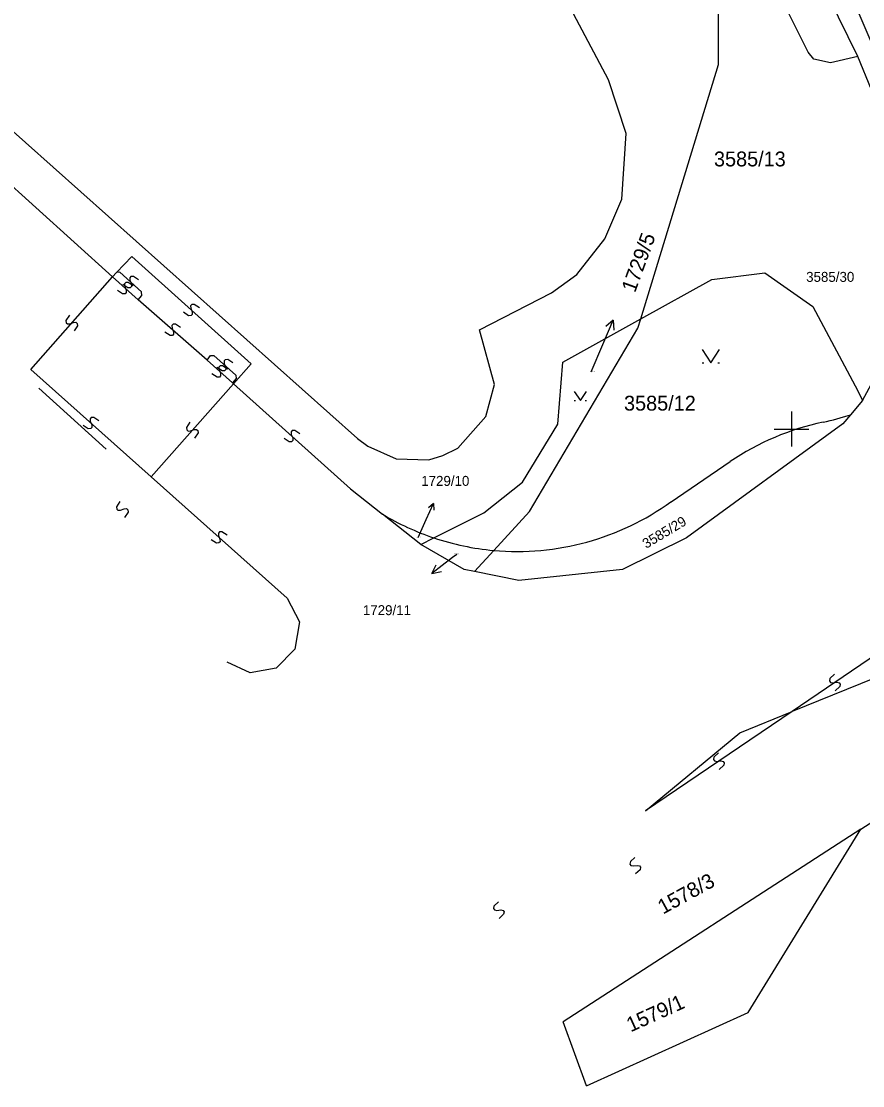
# Model space of a CAD drawing. Extents: x -601196 to -600262, y -1082523 to -1081922.
# Drawn here: x -600494.1 to -600445.9, y -1082437.6 to -1082376.7 of the extents above; entities that cross this region are included whole.
import ezdxf

# ---------------------------------------------------------------- set-up
doc = ezdxf.new("R2010")
doc.units = 0
doc.layers.add('Vrstva 47', color=7, linetype='Continuous')
doc.layers.add('Vrstva 61', color=7, linetype='Continuous')

msp = doc.modelspace()

# ---------------------------------------------------------------- linework, layer by layer
at = {"layer": 'Vrstva 47'}
for p, q in [((-600460.48, -1082380), (-600472.11, -1082358.06)), ((-600446.21, -1082378.67), (-600453.99, -1082362.78)), ((-600449.05, -1082378.42), (-600454.88, -1082366.65)), ((-600454.18, -1082379.12), (-600454.16, -1082370.01)), ((-600439.95, -1082390.82), (-600446.47, -1082375.4)), ((-600499.79, -1082378.34), (-600474.85, -1082400.54)), ((-600448.72, -1082378.83), (-600449.05, -1082378.42)), ((-600446.21, -1082378.67), (-600447.77, -1082379.04)), ((-600444.63, -1082382.49), (-600446.21, -1082378.67)), ((-600458.63, -1082393.69), (-600454.18, -1082379.12)), ((-600447.77, -1082379.04), (-600448.72, -1082378.83)), ((-600488.87, -1082391.28), (-600501.32, -1082380.05)), ((-600459.47, -1082383.07), (-600460.48, -1082380)), ((-600459.72, -1082386.83), (-600459.47, -1082383.07)), ((-600460.68, -1082389.1), (-600459.72, -1082386.83)), ((-600462.3, -1082391.14), (-600460.68, -1082389.1)), ((-600488.65, -1082391.04), (-600487.77, -1082390.11)), ((-600487.77, -1082390.11), (-600480.94, -1082396.26)), ((-600493.55, -1082396.58), (-600488.87, -1082391.28)), ((-600488.87, -1082391.28), (-600488.65, -1082391.04)), ((-600487.4, -1082392.59), (-600488.87, -1082391.28)), ((-600488.46, -1082391.02), (-600488.65, -1082391.04)), ((-600487.21, -1082392.15), (-600488.46, -1082391.02)), ((-600487.815, -1082391.265), (-600487.882, -1082391.339)), ((-600487.882, -1082391.339), (-600487.875, -1082391.48)), ((-600487.674, -1082391.258), (-600487.815, -1082391.265)), ((-600487.381, -1082391.455), (-600487.674, -1082391.258)), ((-600463.75, -1082392.2), (-600462.3, -1082391.14)), ((-600458.63, -1082393.69), (-600454.56, -1082391.43)), ((-600454.56, -1082391.43), (-600451.52, -1082391.05)), ((-600451.52, -1082391.05), (-600448.78, -1082392.98)), ((-600488.293, -1082392.262), (-600488.587, -1082392.067)), ((-600487.995, -1082391.911), (-600488.288, -1082391.714)), ((-600488.117, -1082391.615), (-600488.184, -1082391.689)), ((-600488.184, -1082391.689), (-600488.176, -1082391.831)), ((-600488.176, -1082391.831), (-600488.093, -1082392.038)), ((-600487.976, -1082391.607), (-600488.117, -1082391.615)), ((-600488.093, -1082392.038), (-600488.085, -1082392.18)), ((-600487.854, -1082391.904), (-600487.995, -1082391.911)), ((-600487.682, -1082391.802), (-600487.976, -1082391.607)), ((-600487.875, -1082391.48), (-600487.794, -1082391.689)), ((-600487.787, -1082391.83), (-600487.854, -1082391.904)), ((-600487.794, -1082391.689), (-600487.787, -1082391.83)), ((-600488.152, -1082392.254), (-600488.293, -1082392.262)), ((-600488.085, -1082392.18), (-600488.152, -1082392.254)), ((-600487.4, -1082392.59), (-600487.2, -1082392.36)), ((-600483.45, -1082396.05), (-600487.4, -1082392.59)), ((-600487.2, -1082392.36), (-600487.21, -1082392.15)), ((-600467.87, -1082394.31), (-600463.75, -1082392.2)), ((-600484.336, -1082392.865), (-600484.403, -1082392.939)), ((-600484.403, -1082392.939), (-600484.395, -1082393.08)), ((-600484.395, -1082393.08), (-600484.314, -1082393.289)), ((-600484.195, -1082392.857), (-600484.336, -1082392.865)), ((-600484.314, -1082393.289), (-600484.306, -1082393.43)), ((-600483.901, -1082393.055), (-600484.195, -1082392.857)), ((-600448.78, -1082392.98), (-600446.21, -1082397.8)), ((-600491.344, -1082393.477), (-600491.538, -1082393.773)), ((-600491.538, -1082393.773), (-600491.529, -1082393.914)), ((-600491.313, -1082393.971), (-600491.106, -1082393.888)), ((-600491.106, -1082393.888), (-600490.965, -1082393.879)), ((-600490.965, -1082393.879), (-600490.89, -1082393.945)), ((-600484.514, -1082393.512), (-600484.808, -1082393.314)), ((-600484.373, -1082393.504), (-600484.514, -1082393.512)), ((-600484.306, -1082393.43), (-600484.373, -1082393.504)), ((-600463.09, -1082396.16), (-600458.63, -1082393.69)), ((-600460.8, -1082395.15), (-600460.213, -1082393.769)), ((-600460.213, -1082393.769), (-600460.639, -1082394.131)), ((-600460.213, -1082393.769), (-600460.179, -1082394.327)), ((-600458.8, -1082394.23), (-600458.63, -1082393.69)), ((-600491.529, -1082393.914), (-600491.454, -1082393.98)), ((-600491.454, -1082393.98), (-600491.313, -1082393.971)), ((-600490.881, -1082394.086), (-600491.075, -1082394.382)), ((-600490.89, -1082393.945), (-600490.881, -1082394.086)), ((-600485.58, -1082394.649), (-600485.876, -1082394.456)), ((-600485.41, -1082394), (-600485.476, -1082394.075)), ((-600485.476, -1082394.075), (-600485.467, -1082394.216)), ((-600485.467, -1082394.216), (-600485.382, -1082394.423)), ((-600485.269, -1082393.99), (-600485.41, -1082394)), ((-600485.382, -1082394.423), (-600485.373, -1082394.564)), ((-600484.973, -1082394.183), (-600485.269, -1082393.99)), ((-600467.01, -1082397.45), (-600467.87, -1082394.31)), ((-600465, -1082404.71), (-600458.8, -1082394.23)), ((-600485.439, -1082394.639), (-600485.58, -1082394.649)), ((-600485.373, -1082394.564), (-600485.439, -1082394.639)), ((-600461.47, -1082396.73), (-600460.8, -1082395.15)), ((-600455.12, -1082395.45), (-600454.62, -1082396.2)), ((-600454.62, -1082396.2), (-600454.12, -1082395.45)), ((-600445.94, -1082398.37), (-600444.41, -1082395.51)), ((-600483.45, -1082396.05), (-600483.26, -1082395.79)), ((-600482.01, -1082397.35), (-600483.45, -1082396.05)), ((-600483.26, -1082395.79), (-600483.07, -1082395.78)), ((-600483.07, -1082395.78), (-600481.81, -1082396.91)), ((-600482.421, -1082396.025), (-600482.488, -1082396.099)), ((-600482.488, -1082396.099), (-600482.481, -1082396.241)), ((-600482.481, -1082396.241), (-600482.398, -1082396.448)), ((-600482.28, -1082396.017), (-600482.421, -1082396.025)), ((-600481.986, -1082396.214), (-600482.28, -1082396.017)), ((-600481.95, -1082397.4), (-600480.94, -1082396.26)), ((-600463.38, -1082399.71), (-600463.09, -1082396.16)), ((-600455.12, -1082396.2), (-600455.02, -1082396.2)), ((-600454.22, -1082396.2), (-600454.12, -1082396.2)), ((-600486.66, -1082402.73), (-600493.55, -1082396.58)), ((-600482.89, -1082397.026), (-600483.183, -1082396.829)), ((-600482.599, -1082396.672), (-600482.893, -1082396.475)), ((-600482.71, -1082396.38), (-600482.777, -1082396.454)), ((-600482.777, -1082396.454), (-600482.77, -1082396.595)), ((-600482.77, -1082396.595), (-600482.689, -1082396.804)), ((-600482.682, -1082396.945), (-600482.749, -1082397.019)), ((-600482.569, -1082396.373), (-600482.71, -1082396.38)), ((-600482.689, -1082396.804), (-600482.682, -1082396.945)), ((-600482.458, -1082396.664), (-600482.599, -1082396.672)), ((-600482.276, -1082396.57), (-600482.569, -1082396.373)), ((-600482.391, -1082396.59), (-600482.458, -1082396.664)), ((-600482.398, -1082396.448), (-600482.391, -1082396.59)), ((-600481.81, -1082396.91), (-600481.8, -1082397.1)), ((-600486.66, -1082402.73), (-600481.95, -1082397.4)), ((-600482.749, -1082397.019), (-600482.89, -1082397.026)), ((-600481.8, -1082397.1), (-600482.01, -1082397.35)), ((-600481.95, -1082397.4), (-600482.01, -1082397.35)), ((-600475.25, -1082403.41), (-600481.95, -1082397.4)), ((-600467.5, -1082399.27), (-600467.01, -1082397.45)), ((-600489.24, -1082401.14), (-600493.09, -1082397.66)), ((-600462.44, -1082397.845), (-600462.09, -1082398.37)), ((-600462.09, -1082398.37), (-600461.74, -1082397.845)), ((-600446.21, -1082397.8), (-600445.94, -1082398.37)), ((-600462.44, -1082398.37), (-600462.37, -1082398.37)), ((-600461.81, -1082398.37), (-600461.74, -1082398.37)), ((-600445.94, -1082398.37), (-600446.63, -1082399.18)), ((-600490.087, -1082399.335), (-600490.154, -1082399.409)), ((-600489.946, -1082399.327), (-600490.087, -1082399.335)), ((-600489.652, -1082399.523), (-600489.946, -1082399.327)), ((-600469.11, -1082401.09), (-600467.5, -1082399.27)), ((-600446.63, -1082399.18), (-600447.07, -1082399.7)), ((-600490.263, -1082399.982), (-600490.557, -1082399.786)), ((-600490.122, -1082399.974), (-600490.263, -1082399.982)), ((-600490.154, -1082399.409), (-600490.146, -1082399.551)), ((-600490.146, -1082399.551), (-600490.063, -1082399.758)), ((-600490.055, -1082399.9), (-600490.122, -1082399.974)), ((-600490.063, -1082399.758), (-600490.055, -1082399.9)), ((-600484.439, -1082399.612), (-600484.633, -1082399.908)), ((-600484.633, -1082399.908), (-600484.624, -1082400.049)), ((-600465.4, -1082403.04), (-600463.38, -1082399.71)), ((-600447.07, -1082399.7), (-600456.02, -1082406.23)), ((-600484.624, -1082400.049), (-600484.549, -1082400.115)), ((-600484.549, -1082400.115), (-600484.408, -1082400.106)), ((-600484.408, -1082400.106), (-600484.201, -1082400.023)), ((-600484.201, -1082400.023), (-600484.06, -1082400.014)), ((-600483.976, -1082400.221), (-600484.17, -1082400.517)), ((-600484.06, -1082400.014), (-600483.985, -1082400.08)), ((-600483.985, -1082400.08), (-600483.976, -1082400.221)), ((-600478.759, -1082400.732), (-600479.053, -1082400.535)), ((-600478.581, -1082400.085), (-600478.648, -1082400.159)), ((-600478.648, -1082400.159), (-600478.641, -1082400.301)), ((-600478.641, -1082400.301), (-600478.558, -1082400.509)), ((-600478.44, -1082400.077), (-600478.581, -1082400.085)), ((-600478.558, -1082400.509), (-600478.551, -1082400.65)), ((-600478.146, -1082400.274), (-600478.44, -1082400.077)), ((-600474.85, -1082400.54), (-600474.26, -1082400.98)), ((-600478.618, -1082400.724), (-600478.759, -1082400.732)), ((-600478.551, -1082400.65), (-600478.618, -1082400.724)), ((-600474.26, -1082400.98), (-600472.63, -1082401.7)), ((-600469.97, -1082401.52), (-600469.11, -1082401.09)), ((-600472.63, -1082401.7), (-600470.77, -1082401.76)), ((-600470.77, -1082401.76), (-600469.97, -1082401.52)), ((-600456.9, -1082404.16), (-600453.52, -1082401.86)), ((-600478.87, -1082409.67), (-600486.66, -1082402.73)), ((-600467.62, -1082404.79), (-600465.4, -1082403.04)), ((-600475.25, -1082403.41), (-600473.42, -1082404.87)), ((-600488.448, -1082404.147), (-600488.643, -1082404.442)), ((-600470.91, -1082405.18), (-600470.498, -1082404.263)), ((-600470.498, -1082404.263), (-600470.788, -1082404.5)), ((-600470.498, -1082404.263), (-600470.482, -1082404.637)), ((-600488.643, -1082404.442), (-600488.634, -1082404.584)), ((-600488.634, -1082404.584), (-600488.559, -1082404.65)), ((-600488.559, -1082404.65), (-600488.418, -1082404.641)), ((-600488.418, -1082404.641), (-600488.211, -1082404.558)), ((-600488.211, -1082404.558), (-600488.07, -1082404.549)), ((-600487.986, -1082404.757), (-600488.181, -1082405.052)), ((-600488.07, -1082404.549), (-600487.995, -1082404.615)), ((-600487.995, -1082404.615), (-600487.986, -1082404.757)), ((-600471.23, -1082406.61), (-600473.42, -1082404.87)), ((-600470.47, -1082406.23), (-600467.62, -1082404.79)), ((-600467.05, -1082406.95), (-600465, -1082404.71)), ((-600471.37, -1082406.2), (-600470.91, -1082405.18)), ((-600482.748, -1082405.88), (-600482.814, -1082405.954)), ((-600482.814, -1082405.954), (-600482.806, -1082406.096)), ((-600482.806, -1082406.096), (-600482.723, -1082406.303)), ((-600482.606, -1082405.872), (-600482.748, -1082405.88)), ((-600482.312, -1082406.067), (-600482.606, -1082405.872)), ((-600482.923, -1082406.527), (-600483.217, -1082406.332)), ((-600482.781, -1082406.519), (-600482.923, -1082406.527)), ((-600482.715, -1082406.445), (-600482.781, -1082406.519)), ((-600482.723, -1082406.303), (-600482.715, -1082406.445)), ((-600471.23, -1082406.61), (-600470.47, -1082406.23)), ((-600468.74, -1082408.03), (-600471.23, -1082406.61)), ((-600456.02, -1082406.23), (-600459.67, -1082408.03)), ((-600469.17, -1082407.17), (-600469.4, -1082407.35)), ((-600468.15, -1082408.15), (-600467.05, -1082406.95)), ((-600469.4, -1082407.35), (-600470.588, -1082408.265)), ((-600470.588, -1082408.265), (-600470.344, -1082407.762)), ((-600470.588, -1082408.265), (-600470.039, -1082408.158)), ((-600468.15, -1082408.15), (-600468.74, -1082408.03)), ((-600465.62, -1082408.66), (-600468.15, -1082408.15)), ((-600459.67, -1082408.03), (-600465.62, -1082408.66)), ((-600478.87, -1082409.67), (-600478.17, -1082411.04)), ((-600478.17, -1082411.04), (-600478.43, -1082412.6)), ((-600439.59, -1082411.96), (-600449.97, -1082416.17)), ((-600478.43, -1082412.6), (-600479.51, -1082413.68)), ((-600480.99, -1082413.95), (-600482.31, -1082413.34)), ((-600445.07, -1082412.85), (-600449.97, -1082416.17)), ((-600479.51, -1082413.68), (-600480.99, -1082413.95)), ((-600447.799, -1082414.276), (-600447.825, -1082414.415)), ((-600447.825, -1082414.415), (-600447.769, -1082414.498)), ((-600447.537, -1082414.038), (-600447.799, -1082414.276)), ((-600447.769, -1082414.498), (-600447.63, -1082414.524)), ((-600447.63, -1082414.524), (-600447.409, -1082414.495)), ((-600447.409, -1082414.495), (-600447.27, -1082414.522)), ((-600447.27, -1082414.522), (-600447.214, -1082414.604)), ((-600447.214, -1082414.604), (-600447.24, -1082414.743)), ((-600447.24, -1082414.743), (-600447.502, -1082414.981)), ((-600446.04, -1082422.91), (-600433.76, -1082414.96)), ((-600449.97, -1082416.17), (-600458.36, -1082421.85)), ((-600452.96, -1082417.38), (-600449.97, -1082416.17)), ((-600458.36, -1082421.85), (-600452.96, -1082417.38)), ((-600454.444, -1082418.776), (-600454.47, -1082418.915)), ((-600454.182, -1082418.538), (-600454.444, -1082418.776)), ((-600454.47, -1082418.915), (-600454.414, -1082418.997)), ((-600454.414, -1082418.997), (-600454.275, -1082419.024)), ((-600454.275, -1082419.024), (-600454.054, -1082418.995)), ((-600453.885, -1082419.243), (-600454.147, -1082419.481)), ((-600454.054, -1082418.995), (-600453.915, -1082419.022)), ((-600453.915, -1082419.022), (-600453.859, -1082419.104)), ((-600453.859, -1082419.104), (-600453.885, -1082419.243)), ((-600446.04, -1082422.91), (-600463.07, -1082433.93)), ((-600452.49, -1082433.4), (-600446.04, -1082422.91)), ((-600459.225, -1082424.762), (-600459.251, -1082424.901)), ((-600459.251, -1082424.901), (-600459.194, -1082424.984)), ((-600458.964, -1082424.523), (-600459.225, -1082424.762)), ((-600459.194, -1082424.984), (-600459.055, -1082425.01)), ((-600459.055, -1082425.01), (-600458.834, -1082424.979)), ((-600458.834, -1082424.979), (-600458.695, -1082425.005)), ((-600458.664, -1082425.227), (-600458.925, -1082425.466)), ((-600458.695, -1082425.005), (-600458.638, -1082425.088)), ((-600458.638, -1082425.088), (-600458.664, -1082425.227)), ((-600467.039, -1082427.306), (-600467.065, -1082427.445)), ((-600466.777, -1082427.068), (-600467.039, -1082427.306)), ((-600467.065, -1082427.445), (-600467.009, -1082427.527)), ((-600467.009, -1082427.527), (-600466.87, -1082427.554)), ((-600466.87, -1082427.554), (-600466.649, -1082427.525)), ((-600466.48, -1082427.773), (-600466.742, -1082428.011)), ((-600466.649, -1082427.525), (-600466.51, -1082427.552)), ((-600466.51, -1082427.552), (-600466.454, -1082427.634)), ((-600466.454, -1082427.634), (-600466.48, -1082427.773)), ((-600461.73, -1082437.59), (-600452.49, -1082433.4)), ((-600461.73, -1082437.59), (-600463.07, -1082433.93))]:
    msp.add_line(p, q, dxfattribs=at)
for centre, radius, start, end in [((-600451.925, -1082382.62), 17.386, 282.40549, 287.73149), ((-600445.076, -1082414.359), 15.084, 101.91353, 124.04182), ((-600465.719, -1082391.936), 15.073, 264.93239, 305.80698), ((-600465.618, -1082391.827), 15.198, 239.1147, 251.38429), ((-600465.536, -1082391.277), 15.746, 251.73965, 264.48303)]:
    msp.add_arc(centre, radius, start, end, dxfattribs=at)
at = {"layer": 'Vrstva 61'}
for p, q in [((-600450, -1082399), (-600450, -1082401)), ((-600451, -1082400), (-600449, -1082400))]:
    msp.add_line(p, q, dxfattribs=at)

# ---------------------------------------------------------------- texts
at = {"layer": 'Vrstva 47'}
for s, height, p in [('3585/13', 0.85, (-600454.44, -1082384.96)), ('3585/30', 0.57, (-600449.163, -1082391.57)), ('1729/5', 0.05, (-600461.47, -1082396.73)), ('3585/12', 0.85, (-600459.59, -1082398.94)), ('1729/10', 0.57, (-600471.199, -1082403.25)), ('1729/10', 0.05, (-600471.504, -1082406.2)), ('1729/11', 0.05, (-600469.297, -1082407.17)), ('1729/11', 0.57, (-600474.54, -1082410.65))]:
    msp.add_text(s, height=height, dxfattribs=at).set_placement(p)
for s, height, rotation, p in [('1729/5', 0.85, 70.00002, (-600458.96, -1082392.23)), ('3585/29', 0.57, 30.91284, (-600458.32, -1082406.858)), ('1578/3', 0.85, 28.8, (-600457.36, -1082427.8)), ('1579/1', 0.85, 24.3, (-600459.21, -1082434.54))]:
    msp.add_text(s, height=height, rotation=rotation, dxfattribs=at).set_placement(p)

doc.saveas('drawing.dxf')
